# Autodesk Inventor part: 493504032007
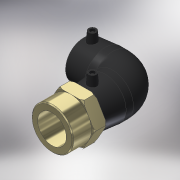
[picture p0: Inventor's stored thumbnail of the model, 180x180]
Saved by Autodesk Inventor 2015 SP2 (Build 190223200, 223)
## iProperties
Created: 2017-06
Part Number: 493504032007
Material: Generic
Description: PLASSON 90° ELBOW FEMALE TRANSITION 32-3/4''
Document SubType Name: Modeling
Designer: KIM
Mass: 131.44 g
Surface Area: 383.023 cm^2
Volume: 131.44 cm^3
Density: 1 g/cm^3
Appearance: Rubber - Black
Author: KIM
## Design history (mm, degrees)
derived "493504.ipt"
feature "Solid1::493504.ipt"
tag "TaggingFeature1"
body "Solid1"
other parameters: "d2" = 44, "d4" = 27.66667, "d5" = 39.6, "d8" = 168 deg, "d10" = 16, "d11" = 5.33333, "d29" = 43, "d30" = 15, "d31" = 45.65, "d34" = 5 deg, "d41" = 4, "d42" = 14, "d43" = 0, "d48" = 61, "d49" = 32, "d50" = 27.2, "d51" = 16, "d54" = 90 deg, "d57" = 32, "d59" = 0, "d61" = 90 deg, "d86" = 3, "d87" = 0, "d93" = 0.1, "d96" = 24.117, "d97" = 23, "d98" = 25, "d99" = 44, "d108" = 0, "d109" = 0.96, "d112" = 45 deg, "d113" = 45 deg, "d114" = 1.6, "d_" = 32, "L_" = 108, "D_" = 23, "A_" = 43, "d_2" = 12, "L_2" = 25, "D_1" = 44, "Rp_" = 24.117
